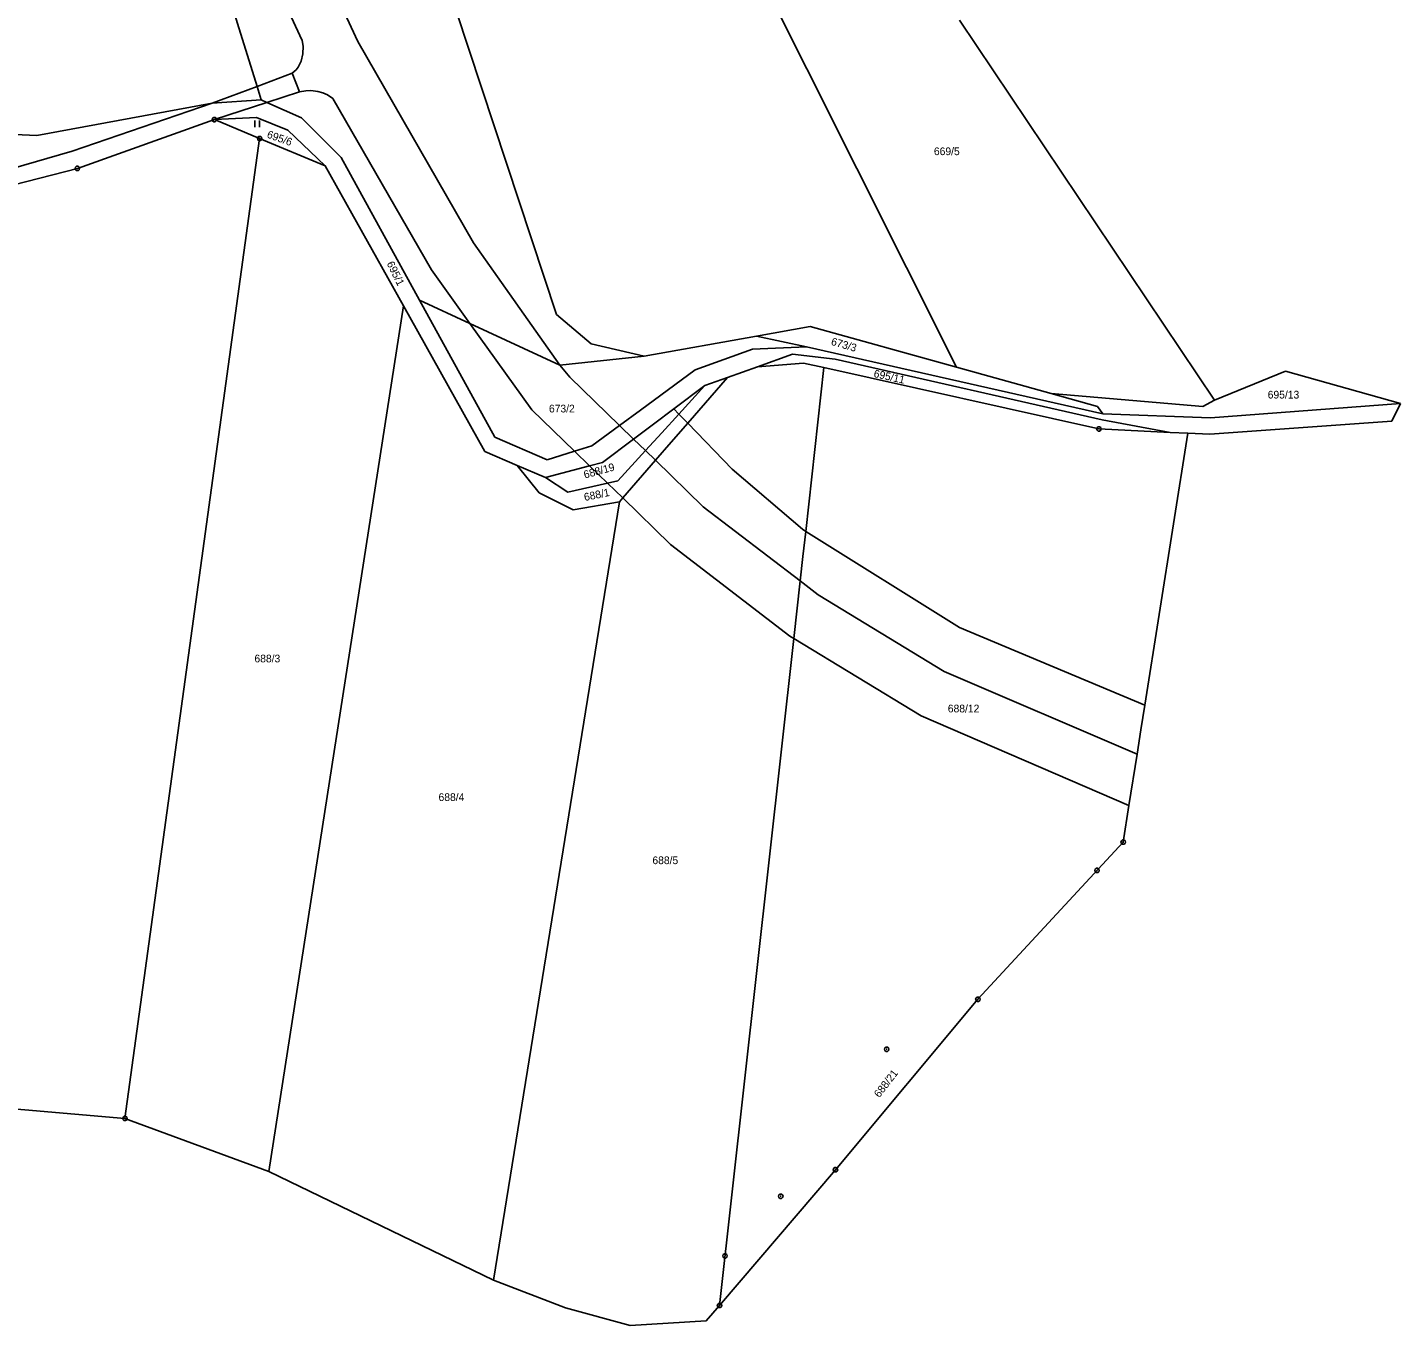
# Model space of a CAD drawing. Extents: x -694465 to -690527, y -983694 to -978978.
# Drawn here: x -693073 to -692770.2, y -983420.1 to -983133.7 of the extents above; entities that cross this region are included whole.
import ezdxf

# ---------------------------------------------------------------- set-up
doc = ezdxf.new("R2010")
doc.units = 0
for name, color, linetype in [('Vrstva 1', 7, 'Continuous'), ('Vrstva 18', 7, 'Continuous'), ('Vrstva 24', 7, 'Continuous'), ('Vrstva 25', 7, 'Continuous')]:
    doc.layers.add(name, color=color, linetype=linetype)

msp = doc.modelspace()

# ---------------------------------------------------------------- linework, layer by layer
at = {"layer": 'Vrstva 1'}
for points in [[(-692955.63, -983208.19), (-692974.61, -983181.207), (-693000.18, -983136.863), (-693061.246, -983005.207), (-693070.091, -982987.841)], [(-693012.431, -983136.594), (-693052.335, -983050.557)], [(-693052.335, -983050.557), (-693022.376, -983146.757)], [(-692956.31, -983197.05), (-692992.22, -983088.37)], [(-692923.12, -983098.95), (-692868.13, -983208.67)], [(-692867.48, -983132.13), (-692811.2, -983215.97)], [(-693014.597, -983143.784), (-693013.744, -983143.07), (-693013.313, -983142.477), (-693012.66, -983141.2), (-693012.289, -983139.577), (-693012.182, -983137.827), (-693012.431, -983136.594)], [(-693022.376, -983146.757), (-693014.597, -983143.784)], [(-693014.597, -983143.784), (-693013.029, -983147.908)], [(-693032.26, -983150.45), (-693022.376, -983146.757)], [(-693022.376, -983146.757), (-693021.45, -983149.73)], [(-693020.22, -983150.277), (-693013.029, -983147.908)], [(-693013.029, -983147.908), (-693011.591, -983147.7), (-693010.508, -983147.66), (-693009.001, -983147.876), (-693007.878, -983148.131), (-693006.828, -983148.561), (-693005.647, -983149.404)], [(-692975.437, -983199.027), (-692983.87, -983187.169), (-693005.647, -983149.404)], [(-693070.96, -983157.56), (-693032.26, -983150.45)], [(-693032.26, -983150.45), (-693063.13, -983161.05)], [(-693021.45, -983149.73), (-693032.26, -983150.45)], [(-693031.78, -983154.06), (-693020.22, -983150.277)], [(-693021.45, -983149.73), (-693020.22, -983150.277)], [(-693020.22, -983150.277), (-693012.57, -983153.68)], [(-693062.01, -983164.84), (-693031.78, -983154.06)], [(-693031.78, -983154.06), (-693022.49, -983153.62)], [(-693031.78, -983154.06), (-693021.8, -983158.23)], [(-693022.49, -983153.62), (-693015.59, -983156.41)], [(-693012.57, -983153.68), (-693003.8, -983162.43)], [(-693078.94, -983157.17), (-693070.96, -983157.56)], [(-693021.8, -983158.23), (-693051.51, -983374.36)], [(-693021.8, -983158.23), (-693007.36, -983164.27)], [(-693015.59, -983156.41), (-693007.36, -983164.27)], [(-693063.13, -983161.05), (-693076.57, -983164.92)], [(-693007.36, -983164.27), (-692990.11, -983195.14)], [(-693003.8, -983162.43), (-692986.52, -983193.9)], [(-693076.01, -983168.45), (-693062.01, -983164.84)], [(-692986.52, -983193.9), (-692969.93, -983224.11)], [(-692986.52, -983193.9), (-692975.437, -983199.027)], [(-692990.11, -983195.14), (-693019.76, -983386.04)], [(-692990.11, -983195.14), (-692972.16, -983227.26)], [(-692948.69, -983203.54), (-692956.31, -983197.05)], [(-692975.437, -983199.027), (-692955.63, -983208.19)], [(-692952.366, -983227.214), (-692961.78, -983218.046), (-692975.437, -983199.027)], [(-692900.37, -983199.71), (-692912.21, -983201.83)], [(-692868.13, -983208.67), (-692900.37, -983199.71)], [(-692936.99, -983206.27), (-692948.69, -983203.54)], [(-692912.21, -983201.83), (-692936.99, -983206.27)], [(-692912.21, -983201.83), (-692901.18, -983204.18)], [(-692955.63, -983208.19), (-692936.99, -983206.27)], [(-692925.77, -983209.24), (-692913.11, -983204.71)], [(-692913.11, -983204.71), (-692901.18, -983204.18)], [(-692904.26, -983205.82), (-692912, -983208.58)], [(-692894.88, -983206.87), (-692904.26, -983205.82)], [(-692901.18, -983204.18), (-692835.82, -983218.96)], [(-692836, -983220.29), (-692894.88, -983206.87)], [(-692942.403, -983221.502), (-692953.406, -983210.846), (-692955.63, -983208.19)], [(-692937.836, -983218.135), (-692925.77, -983209.24)], [(-692918.64, -983210.95), (-692912, -983208.58)], [(-692912, -983208.58), (-692901.82, -983207.76)], [(-692901.82, -983207.76), (-692897.34, -983208.76)], [(-692901.364, -983244.888), (-692897.34, -983208.76)], [(-692897.34, -983208.76), (-692836.7, -983222.3)], [(-692847.22, -983214.48), (-692868.13, -983208.67)], [(-692811.2, -983215.97), (-692795.54, -983209.52)], [(-692795.54, -983209.52), (-692770.18, -983216.71)], [(-692930.452, -983217.852), (-692923.61, -983212.72)], [(-692929.345, -983219.012), (-692923.61, -983212.72)], [(-692927.4, -983221.03), (-692918.64, -983210.95)], [(-692923.61, -983212.72), (-692918.64, -983210.95)], [(-692836.99, -983217.33), (-692847.22, -983214.48)], [(-692847.22, -983214.48), (-692813.81, -983217.32)], [(-692813.81, -983217.32), (-692811.2, -983215.97)], [(-692942.403, -983221.502), (-692937.836, -983218.135)], [(-692934.925, -983221.207), (-692930.452, -983217.852)], [(-692933.116, -983223.149), (-692929.345, -983219.012)], [(-692929.345, -983219.012), (-692930.452, -983217.852)], [(-692927.4, -983221.03), (-692929.345, -983219.012)], [(-692835.82, -983218.96), (-692836.99, -983217.33)], [(-692812.09, -983219.87), (-692835.82, -983218.96)], [(-692770.18, -983216.71), (-692772.1, -983220.59), (-692812.24, -983223.47), (-692817.09, -983223.24)], [(-692770.18, -983216.71), (-692812.09, -983219.87)], [(-692948.53, -983226.02), (-692942.403, -983221.502)], [(-692939.331, -983224.511), (-692942.403, -983221.502)], [(-692939.331, -983224.511), (-692934.925, -983221.207)], [(-692931.014, -983225.189), (-692927.4, -983221.03)], [(-692901.364, -983244.888), (-692902.091, -983244.425), (-692917.602, -983231.189), (-692927.4, -983221.03)], [(-692821, -983223.05), (-692836, -983220.29)], [(-692969.93, -983224.11), (-692958.36, -983229.08)], [(-692946.21, -983229.67), (-692939.331, -983224.511)], [(-692936.684, -983227.063), (-692939.331, -983224.511)], [(-692936.684, -983227.063), (-692933.116, -983223.149)], [(-692836.7, -983222.3), (-692821, -983223.05)], [(-692817.09, -983223.24), (-692826.575, -983283.226)], [(-692821, -983223.05), (-692817.09, -983223.24)], [(-692972.16, -983227.26), (-692965, -983230.32)], [(-692958.36, -983229.08), (-692952.366, -983227.214)], [(-692952.366, -983227.214), (-692948.53, -983226.02)], [(-692949.07, -983230.427), (-692952.366, -983227.214)], [(-692942.77, -983233.74), (-692936.684, -983227.063)], [(-692934.492, -983229.191), (-692936.684, -983227.063)], [(-692934.492, -983229.191), (-692931.014, -983225.189)], [(-692965, -983230.32), (-692960.18, -983236.39)], [(-692965, -983230.32), (-692958.76, -983232.99)], [(-692958.76, -983232.99), (-692949.07, -983230.427)], [(-692949.07, -983230.427), (-692946.21, -983229.67)], [(-692945.1, -983234.274), (-692949.07, -983230.427)], [(-692941.722, -983237.511), (-692934.492, -983229.191)], [(-692902.579, -983255.802), (-692923.983, -983239.451), (-692934.492, -983229.191)], [(-692958.76, -983232.99), (-692953.8, -983236.27)], [(-692945.1, -983234.274), (-692942.77, -983233.74)], [(-692960.18, -983236.39), (-692952.63, -983240.12)], [(-692953.8, -983236.27), (-692945.1, -983234.274)], [(-692941.722, -983237.511), (-692945.1, -983234.274)], [(-692942.46, -983238.36), (-692970.23, -983410.06)], [(-692952.63, -983240.12), (-692942.46, -983238.36)], [(-692942.46, -983238.36), (-692941.722, -983237.511)], [(-692903.995, -983268.513), (-692904.868, -983267.977), (-692931.189, -983247.787), (-692941.722, -983237.511)], [(-692901.982, -983250.44), (-692901.364, -983244.888)], [(-692826.575, -983283.226), (-692867.42, -983266.105), (-692901.364, -983244.888)], [(-692902.579, -983255.802), (-692901.982, -983250.44)], [(-692903.995, -983268.513), (-692902.579, -983255.802)], [(-692828.285, -983294.045), (-692870.822, -983275.756), (-692898.65, -983258.883), (-692902.579, -983255.802)], [(-692920.38, -983415.62), (-692903.995, -983268.513)], [(-692830.071, -983305.342), (-692875.878, -983285.556), (-692903.995, -983268.513)], [(-692826.575, -983283.226), (-692827.439, -983288.693)], [(-692827.439, -983288.693), (-692828.285, -983294.045)], [(-692828.285, -983294.045), (-692830.071, -983305.342)], [(-692830.071, -983305.342), (-692831.35, -983313.43), (-692863.39, -983348.08), (-692894.8, -983385.69), (-692920.38, -983415.62)], [(-693051.51, -983374.36), (-693084.72, -983371.54)], [(-693019.76, -983386.04), (-693051.51, -983374.36)], [(-692970.23, -983410.06), (-693019.76, -983386.04)], [(-692920.38, -983415.62), (-692923.31, -983418.99), (-692940.05, -983420.05), (-692954.36, -983416.16), (-692970.23, -983410.06)]]:
    msp.add_lwpolyline(points, dxfattribs=at)
at = {"layer": 'Vrstva 24'}
for points in [[(-693031.626, -983153.584), (-693031.376, -983153.766), (-693031.28, -983154.06), (-693031.376, -983154.354), (-693031.626, -983154.536), (-693031.934, -983154.536), (-693032.184, -983154.354), (-693032.28, -983154.06), (-693032.184, -983153.766), (-693031.934, -983153.584)], [(-693021.646, -983157.754), (-693021.396, -983157.936), (-693021.3, -983158.23), (-693021.396, -983158.524), (-693021.646, -983158.706), (-693021.954, -983158.706), (-693022.204, -983158.524), (-693022.3, -983158.23), (-693022.204, -983157.936), (-693021.954, -983157.754)], [(-693061.856, -983164.364), (-693061.606, -983164.546), (-693061.51, -983164.84), (-693061.606, -983165.134), (-693061.856, -983165.316), (-693062.164, -983165.316), (-693062.414, -983165.134), (-693062.51, -983164.84), (-693062.414, -983164.546), (-693062.164, -983164.364)], [(-692836.546, -983221.824), (-692836.296, -983222.006), (-692836.2, -983222.3), (-692836.296, -983222.594), (-692836.546, -983222.776), (-692836.854, -983222.776), (-692837.104, -983222.594), (-692837.2, -983222.3), (-692837.104, -983222.006), (-692836.854, -983221.824)], [(-692831.196, -983312.954), (-692830.946, -983313.136), (-692830.85, -983313.43), (-692830.946, -983313.724), (-692831.196, -983313.906), (-692831.504, -983313.906), (-692831.754, -983313.724), (-692831.85, -983313.43), (-692831.754, -983313.136), (-692831.504, -983312.954)], [(-692836.976, -983319.204), (-692836.726, -983319.386), (-692836.63, -983319.68), (-692836.726, -983319.974), (-692836.976, -983320.156), (-692837.284, -983320.156), (-692837.534, -983319.974), (-692837.63, -983319.68), (-692837.534, -983319.386), (-692837.284, -983319.204)], [(-692863.236, -983347.604), (-692862.986, -983347.786), (-692862.89, -983348.08), (-692862.986, -983348.374), (-692863.236, -983348.556), (-692863.544, -983348.556), (-692863.794, -983348.374), (-692863.89, -983348.08), (-692863.794, -983347.786), (-692863.544, -983347.604)], [(-692883.346, -983358.644), (-692883.096, -983358.826), (-692883, -983359.12), (-692883.096, -983359.414), (-692883.346, -983359.596), (-692883.654, -983359.596), (-692883.904, -983359.414), (-692884, -983359.12), (-692883.904, -983358.826), (-692883.654, -983358.644)], [(-693051.356, -983373.884), (-693051.106, -983374.066), (-693051.01, -983374.36), (-693051.106, -983374.654), (-693051.356, -983374.836), (-693051.664, -983374.836), (-693051.914, -983374.654), (-693052.01, -983374.36), (-693051.914, -983374.066), (-693051.664, -983373.884)], [(-692894.646, -983385.214), (-692894.396, -983385.396), (-692894.3, -983385.69), (-692894.396, -983385.984), (-692894.646, -983386.166), (-692894.954, -983386.166), (-692895.204, -983385.984), (-692895.3, -983385.69), (-692895.204, -983385.396), (-692894.954, -983385.214)], [(-692906.716, -983391.074), (-692906.466, -983391.256), (-692906.37, -983391.55), (-692906.466, -983391.844), (-692906.716, -983392.026), (-692907.024, -983392.026), (-692907.274, -983391.844), (-692907.37, -983391.55), (-692907.274, -983391.256), (-692907.024, -983391.074)], [(-692919.006, -983404.214), (-692918.756, -983404.396), (-692918.66, -983404.69), (-692918.756, -983404.984), (-692919.006, -983405.166), (-692919.314, -983405.166), (-692919.564, -983404.984), (-692919.66, -983404.69), (-692919.564, -983404.396), (-692919.314, -983404.214)], [(-692920.226, -983415.144), (-692919.976, -983415.326), (-692919.88, -983415.62), (-692919.976, -983415.914), (-692920.226, -983416.096), (-692920.534, -983416.096), (-692920.784, -983415.914), (-692920.88, -983415.62), (-692920.784, -983415.326), (-692920.534, -983415.144)]]:
    msp.add_lwpolyline(points, close=True, dxfattribs=at)
for points in [[(-693031.899, -983154.06), (-693031.66, -983154.06)], [(-693021.919, -983158.23), (-693021.68, -983158.23)], [(-693062.129, -983164.84), (-693061.89, -983164.84)], [(-692836.819, -983222.3), (-692836.58, -983222.3)], [(-692831.469, -983313.43), (-692831.23, -983313.43)], [(-692837.249, -983319.68), (-692837.01, -983319.68)], [(-692863.509, -983348.08), (-692863.27, -983348.08)], [(-692883.619, -983359.12), (-692883.38, -983359.12)], [(-693051.629, -983374.36), (-693051.39, -983374.36)], [(-692894.919, -983385.69), (-692894.68, -983385.69)], [(-692906.989, -983391.55), (-692906.75, -983391.55)], [(-692919.279, -983404.69), (-692919.04, -983404.69)], [(-692920.499, -983415.62), (-692920.26, -983415.62)]]:
    msp.add_lwpolyline(points, dxfattribs=at)
at = {"layer": 'Vrstva 25'}
for points in [[(-693022.87, -983154.24), (-693022.87, -983155.74)], [(-693021.87, -983155.74), (-693021.87, -983154.24)]]:
    msp.add_lwpolyline(points, dxfattribs=at)

# ---------------------------------------------------------------- texts
at = {"layer": 'Vrstva 18'}
for s, rotation, p in [('695/6', 340.22234, (-693020.345, -983157.982)), ('695/1', 296.10459, (-692993.828, -983185.807)), ('673/3', 343.77468, (-692895.907, -983203.71)), ('695/11', 347.38431, (-692886.492, -983210.818)), ('688/19', 15.29797, (-692950.076, -983233.246)), ('688/1', 11.68834, (-692950.08, -983238.198)), ('688/21', 52.31105, (-692885.135, -983369.907))]:
    msp.add_text(s, height=1.7, rotation=rotation, dxfattribs=at).set_placement(p)
for s, p in [('669/5', (-692873.093, -983161.9)), ('695/13', (-692799.473, -983215.58)), ('673/2', (-692957.993, -983218.65)), ('688/3', (-693022.943, -983273.78)), ('688/12', (-692870.023, -983284.81)), ('688/4', (-692982.343, -983304.35)), ('688/5', (-692935.173, -983318.28))]:
    msp.add_text(s, height=1.7, dxfattribs=at).set_placement(p)

doc.saveas('drawing.dxf')
